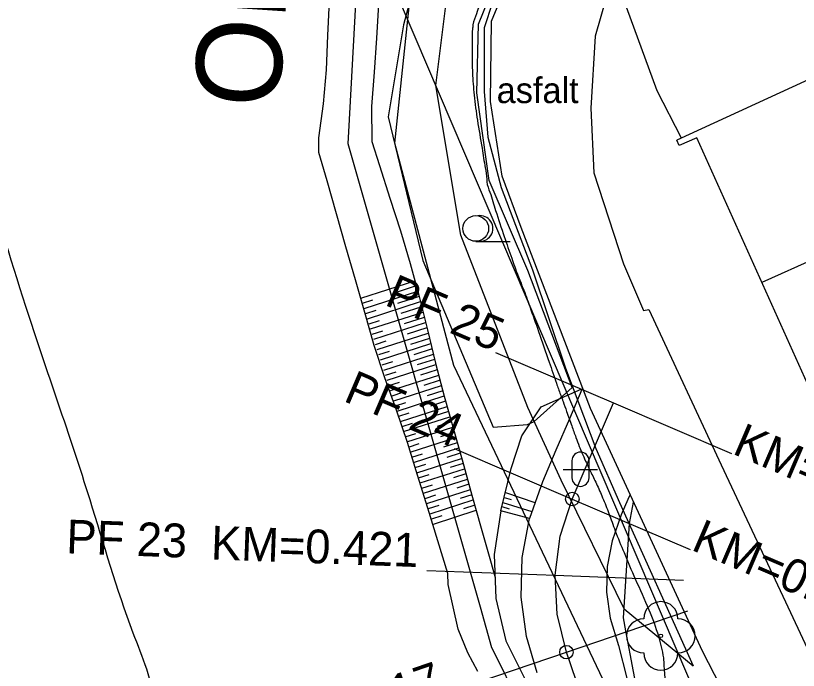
# Model space of a CAD drawing. Extents: x -478102 to -473059, y -1117705 to -1114104.
# Drawn here: x -476531.57 to -476485.84, y -1116837.52 to -1116799.24 of the extents above; entities that cross this region are included whole.
import ezdxf

# ---------------------------------------------------------------- set-up
doc = ezdxf.new("R2010")
doc.units = 0
for name, color, linetype in [('Budovy', 7, 'Continuous'), ('cestn___p____kop', 7, 'Continuous'), ('cesty', 7, 'Continuous'), ('hrana_L', 7, 'Continuous'), ('HraniceSouvislehoPorostu', 7, 'Continuous'), ('ObPÚ', 7, 'Continuous'), ('Ploty', 7, 'Continuous'), ('POLYGONY_SITUACE_PF', 7, 'Continuous'), ('POLYGONY_SITUACE_PF_POPISY', 7, 'Continuous'), ('POLYGONY_SITUACE_PO', 7, 'Continuous'), ('PopisneZnackyKultura', 7, 'Continuous'), ('PopisPovrchu', 7, 'Continuous'), ('RozhraniKultur', 7, 'Continuous'), ('RozhraniVozovky', 7, 'Continuous'), ('Teren_HranaSvahu', 7, 'Continuous'), ('Teren_PataSvahu', 7, 'Continuous'), ('TP_HS', 7, 'Continuous'), ('Vrstevnice_hlavni', 7, 'Continuous'), ('Vrstevnice_vedlejsi', 7, 'Continuous'), ('ZnackyStromu', 7, 'Continuous')]:
    doc.layers.add(name, color=color, linetype=linetype)

msp = doc.modelspace()

# ---------------------------------------------------------------- linework, layer by layer
for p, q in [((-476513.342, -1116800.401), (-476513.245, -1116798.403)), ((-476510.367, -1116798.561), (-476510.489, -1116800.557)), ((-476513.414, -1116802.4), (-476513.342, -1116800.401)), ((-476510.489, -1116800.557), (-476510.631, -1116802.552)), ((-476513.593, -1116804.393), (-476513.414, -1116802.4)), ((-476510.631, -1116802.552), (-476510.773, -1116804.548)), ((-476513.863, -1116806.381), (-476513.593, -1116804.393)), ((-476510.773, -1116804.548), (-476510.764, -1116806.596)), ((-476513.851, -1116807.251), (-476513.863, -1116806.381)), ((-476510.764, -1116806.596), (-476510.312, -1116808.011)), ((-476513.377, -1116808.907), (-476513.851, -1116807.251)), ((-476510.312, -1116808.011), (-476509.703, -1116809.917)), ((-476512.827, -1116810.83), (-476513.377, -1116808.907)), ((-476509.703, -1116809.917), (-476509.094, -1116811.822)), ((-476512.277, -1116812.753), (-476512.827, -1116810.83)), ((-476509.094, -1116811.822), (-476508.515, -1116813.737)), ((-476511.727, -1116814.676), (-476512.277, -1116812.753)), ((-476508.515, -1116813.737), (-476507.995, -1116815.669)), ((-476511.176, -1116816.599), (-476511.727, -1116814.676)), ((-476507.995, -1116815.669), (-476507.517, -1116817.612)), ((-476510.626, -1116818.521), (-476511.176, -1116816.599)), ((-476507.517, -1116817.612), (-476507.038, -1116819.556)), ((-476510, -1116820.422), (-476510.626, -1116818.521)), ((-476507.038, -1116819.556), (-476506.536, -1116821.493)), ((-476509.328, -1116822.309), (-476510, -1116820.422)), ((-476506.536, -1116821.493), (-476505.995, -1116823.419)), ((-476508.674, -1116824.202), (-476509.328, -1116822.309)), ((-476505.995, -1116823.419), (-476505.454, -1116825.344)), ((-476508.087, -1116826.114), (-476508.674, -1116824.202)), ((-476505.454, -1116825.344), (-476504.913, -1116827.27)), ((-476507.5, -1116828.026), (-476508.087, -1116826.114)), ((-476504.913, -1116827.27), (-476504.372, -1116829.196)), ((-476506.913, -1116829.938), (-476507.5, -1116828.026)), ((-476504.372, -1116829.196), (-476503.832, -1116831.121)), ((-476506.326, -1116831.85), (-476506.913, -1116829.938)), ((-476503.832, -1116831.121), (-476503.562, -1116832.084)), ((-476506.297, -1116832.488), (-476506.326, -1116831.85)), ((-476504.565, -1116837.587), (-476505.152, -1116836.498))]:
    msp.add_line(p, q)
for points in [[(-476511.41, -1116815.758), (-476508.245, -1116814.74)], [(-476508.163, -1116815.045), (-476509.461, -1116815.462)], [(-476511.217, -1116816.358), (-476508.081, -1116815.35)], [(-476511.314, -1116816.058), (-476510.696, -1116815.859)], [(-476511.025, -1116816.958), (-476507.923, -1116815.961)], [(-476507.999, -1116815.654), (-476509.268, -1116816.062)], [(-476511.121, -1116816.658), (-476510.503, -1116816.459)], [(-476507.848, -1116816.268), (-476509.075, -1116816.662)], [(-476510.832, -1116817.558), (-476507.772, -1116816.575)], [(-476507.697, -1116816.882), (-476508.882, -1116817.263)], [(-476510.928, -1116817.258), (-476510.31, -1116817.06)], [(-476510.639, -1116818.158), (-476507.621, -1116817.188)], [(-476510.735, -1116817.858), (-476510.117, -1116817.66)], [(-476510.446, -1116818.759), (-476507.47, -1116817.802)], [(-476507.546, -1116817.495), (-476508.689, -1116817.863)], [(-476510.542, -1116818.458), (-476509.924, -1116818.26)], [(-476507.395, -1116818.109), (-476508.496, -1116818.463)], [(-476510.253, -1116819.359), (-476507.319, -1116818.416)], [(-476507.243, -1116818.723), (-476508.303, -1116819.063)], [(-476510.349, -1116819.059), (-476509.732, -1116818.86)], [(-476510.06, -1116819.959), (-476507.168, -1116819.029)], [(-476510.156, -1116819.659), (-476509.539, -1116819.46)], [(-476509.867, -1116820.559), (-476507.016, -1116819.643)], [(-476507.092, -1116819.336), (-476508.11, -1116819.663)], [(-476509.964, -1116820.259), (-476509.346, -1116820.06)], [(-476506.936, -1116819.948), (-476507.917, -1116820.263)], [(-476509.674, -1116821.159), (-476506.857, -1116820.254)], [(-476506.778, -1116820.559), (-476507.724, -1116820.864)], [(-476509.771, -1116820.859), (-476509.153, -1116820.661)], [(-476509.481, -1116821.759), (-476506.699, -1116820.865)], [(-476509.578, -1116821.459), (-476508.96, -1116821.261)], [(-476509.288, -1116822.36), (-476506.54, -1116821.476)], [(-476506.62, -1116821.171), (-476507.531, -1116821.464)], [(-476509.385, -1116822.06), (-476508.767, -1116821.861)], [(-476506.455, -1116821.78), (-476507.338, -1116822.064)], [(-476509.192, -1116822.66), (-476508.574, -1116822.461)], [(-476509.095, -1116822.96), (-476506.37, -1116822.084)], [(-476506.285, -1116822.388), (-476507.146, -1116822.664)], [(-476508.903, -1116823.56), (-476506.199, -1116822.691)], [(-476508.999, -1116823.26), (-476508.381, -1116823.061)], [(-476508.71, -1116824.16), (-476506.029, -1116823.299)], [(-476506.114, -1116822.995), (-476506.953, -1116823.264)], [(-476508.806, -1116823.86), (-476508.188, -1116823.662)], [(-476505.944, -1116823.602), (-476506.76, -1116823.865)], [(-476508.613, -1116824.46), (-476507.995, -1116824.262)], [(-476508.517, -1116824.76), (-476505.858, -1116823.906)], [(-476505.773, -1116824.21), (-476506.567, -1116824.465)], [(-476508.324, -1116825.361), (-476505.687, -1116824.513)], [(-476508.42, -1116825.06), (-476507.802, -1116824.862)], [(-476508.131, -1116825.961), (-476505.517, -1116825.121)], [(-476505.602, -1116824.817), (-476506.374, -1116825.065)], [(-476508.227, -1116825.661), (-476507.61, -1116825.462)], [(-476505.431, -1116825.424), (-476506.181, -1116825.665)], [(-476508.034, -1116826.261), (-476507.417, -1116826.062)], [(-476507.938, -1116826.561), (-476505.346, -1116825.728)], [(-476505.261, -1116826.032), (-476505.988, -1116826.265)], [(-476507.745, -1116827.161), (-476505.176, -1116826.335)], [(-476507.842, -1116826.861), (-476507.224, -1116826.662)], [(-476507.552, -1116827.761), (-476505.005, -1116826.943)], [(-476505.09, -1116826.639), (-476505.795, -1116826.865)], [(-476507.649, -1116827.461), (-476507.031, -1116827.263)], [(-476504.92, -1116827.246), (-476505.602, -1116827.466)], [(-476507.456, -1116828.061), (-476506.838, -1116827.863)], [(-476507.359, -1116828.361), (-476504.834, -1116827.55)], [(-476504.749, -1116827.854), (-476505.409, -1116828.066)], [(-476493.611, -1116845.046), (-476495.024, -1116839.954), (-476495.915, -1116835.202), (-476496.059, -1116834.438), (-476495.701, -1116828.922), (-476495.475, -1116827.69)], [(-476507.166, -1116828.962), (-476504.664, -1116828.157)], [(-476507.263, -1116828.662), (-476506.645, -1116828.463)], [(-476505.152, -1116836.498), (-476505.719, -1116835.11), (-476506.297, -1116832.488)]]:
    msp.add_lwpolyline(points)
at = {"layer": 'Budovy'}
for p, q in [((-476480.507, -1116800.783), (-476492.94, -1116806.52)), ((-476491.78, -1116806.38), (-476492.81, -1116806.83)), ((-476478.1, -1116836.8), (-476491.78, -1116806.38)), ((-476492.81, -1116806.83), (-476492.94, -1116806.52)), ((-476483.847, -1116812.976), (-476487.978, -1116814.834))]:
    msp.add_line(p, q, dxfattribs=at)
at = {"layer": 'cestn___p____kop'}
for p, q in [((-476503.037, -1116827.414), (-476502.619, -1116827.536)), ((-476502.958, -1116827.111), (-476501.236, -1116827.702)), ((-476503.162, -1116827.938), (-476502.73, -1116828.066)), ((-476503.109, -1116827.712), (-476501.413, -1116828.222))]:
    msp.add_line(p, q, dxfattribs=at)
at = {"layer": 'cesty'}
for p, q in [((-476495.672, -1116827.229), (-476495.799, -1116827.525)), ((-476495.799, -1116827.525), (-476496.187, -1116828.43)), ((-476501.559, -1116828.638), (-476503.234, -1116828.185)), ((-476496.187, -1116828.43), (-476496.729, -1116829.943)), ((-476496.729, -1116829.943), (-476497.006, -1116831.435)), ((-476497.006, -1116831.435), (-476497.042, -1116832.952)), ((-476497.042, -1116832.952), (-476496.836, -1116834.458)), ((-476496.836, -1116834.458), (-476496.354, -1116836.065)), ((-476502.931, -1116835.794), (-476502.931, -1116835.794)), ((-476502.931, -1116835.794), (-476499.157, -1116843.34)), ((-476496.354, -1116836.065), (-476495.859, -1116837.974)), ((-476501.482, -1116840.818), (-476503.246, -1116837.201))]:
    msp.add_line(p, q, dxfattribs=at)
for points in [[(-476500.872, -1116822.107), (-476498.541, -1116821.07)], [(-476501.995, -1116823.801), (-476500.872, -1116822.107)], [(-476502.628, -1116825.706), (-476501.995, -1116823.801)], [(-476503.234, -1116828.185), (-476502.628, -1116825.706)], [(-476503.234, -1116828.185), (-476503.614, -1116830.746)], [(-476501.983, -1116830.916), (-476501.559, -1116828.638)], [(-476503.614, -1116830.746), (-476503.515, -1116833.316)], [(-476502.038, -1116833.233), (-476501.983, -1116830.916)], [(-476503.515, -1116833.316), (-476502.931, -1116835.794)], [(-476501.723, -1116835.529), (-476502.038, -1116833.233)], [(-476501.093, -1116837.661), (-476501.723, -1116835.529)], [(-476502.931, -1116835.794), (-476502.931, -1116835.794)]]:
    msp.add_lwpolyline(points, dxfattribs=at)
at = {"layer": 'hrana_L'}
for points in [[(-476498.486, -1116821.093), (-476499.222, -1116822.813)], [(-476499.222, -1116822.813), (-476500.009, -1116824.652)], [(-476500.009, -1116824.652), (-476500.796, -1116826.49)], [(-476500.796, -1116826.49), (-476501.559, -1116828.638)]]:
    msp.add_lwpolyline(points, dxfattribs=at)
at = {"layer": 'HraniceSouvislehoPorostu'}
msp.add_lwpolyline([(-476503.667, -1116823.297), (-476501.663, -1116823.142), (-476501.269, -1116822.977), (-476499.06, -1116820.987), (-476501.643, -1116814.144), (-476503.911, -1116808.879), (-476504.635, -1116803.762), (-476504.524, -1116799.738), (-476502.429, -1116794.533), (-476499.158, -1116791.112), (-476500.941, -1116790.007), (-476502.678, -1116789.287), (-476504.94, -1116790.065), (-476506.236, -1116792.421), (-476507.371, -1116793.97), (-476508.92, -1116799.781), (-476509.8, -1116805.165), (-476507.792, -1116813.551)], close=True, dxfattribs=at)
at = {"layer": 'ObPÚ'}
msp.add_lwpolyline([(-476357.4, -1116837.74), (-476422.93, -1116845.91), (-476427.37, -1116819.37), (-476430.29, -1116820.37), (-476436.91, -1116823.52), (-476455.71, -1116831.67), (-476450.1, -1116844.01), (-476476.04, -1116849.41), (-476482.1, -1116843.09), (-476483.67, -1116843.77), (-476488.84, -1116845.93), (-476490.13, -1116842.91), (-476508.98, -1116798.77)], dxfattribs=at)
at = {"layer": 'Ploty'}
msp.add_lwpolyline([(-476492.676, -1116806.398), (-476494.1, -1116803.644), (-476496.089, -1116798.145), (-476495.288, -1116796.97), (-476493.089, -1116793.815), (-476489.802, -1116790.11), (-476487.243, -1116787.893)], dxfattribs=at)
at = {"layer": 'POLYGONY_SITUACE_PF'}
for points in [[(-476503.542, -1116818.929), (-476496.647, -1116821.88), (-476489.752, -1116824.832)], [(-476505.947, -1116824.548), (-476499.052, -1116827.5), (-476492.157, -1116830.451)], [(-476507.547, -1116831.679), (-476500.052, -1116831.956), (-476492.557, -1116832.234)], [(-476506.491, -1116838.872), (-476499.392, -1116836.452), (-476492.293, -1116834.032)]]:
    msp.add_lwpolyline(points, dxfattribs=at)
at = {"layer": 'POLYGONY_SITUACE_PO'}
for points in [[(-476503.246, -1116837.201), (-476503.754, -1116836.198), (-476504.411, -1116833.82), (-476512.149, -1116806.742), (-476511.387, -1116792.829)], [(-476301.427, -1117045.065), (-476372.905, -1117052.019), (-476378.974, -1117051.908), (-476382.069, -1117051.436), (-476384.865, -1117050.444), (-476390.281, -1117047.7), (-476394.946, -1117043.817), (-476398.626, -1117038.989), (-476458.957, -1116938.029), (-476465.394, -1116926.586), (-476471.221, -1116914.82), (-476476.422, -1116902.765), (-476480.983, -1116890.454), (-476499.392, -1116836.452), (-476499.929, -1116834.228), (-476500.052, -1116831.944), (-476499.756, -1116829.676), (-476499.052, -1116827.5), (-476496.647, -1116821.88)]]:
    msp.add_lwpolyline(points, dxfattribs=at)
for centre in [(-476499.052, -1116827.5), (-476499.392, -1116836.452)]:
    msp.add_circle(centre, 0.395, dxfattribs=at)
at = {"layer": 'PopisneZnackyKultura'}
for p, q in [((-476504.689, -1116812.435), (-476502.689, -1116812.435)), ((-476499.077, -1116825.265), (-476499.077, -1116826.265)), ((-476498.077, -1116825.265), (-476498.077, -1116826.265)), ((-476499.577, -1116825.765), (-476497.577, -1116825.765))]:
    msp.add_line(p, q, dxfattribs=at)
msp.add_circle((-476504.689, -1116811.684), 0.75, dxfattribs=at)
for centre, radius, start, end in [((-476504.439, -1116811.684), 0.75, 260.4059, 99.5941), ((-476498.568, -1116825.258), 0.5, 0, 180), ((-476498.568, -1116826.258), 0.5, 180, 0)]:
    msp.add_arc(centre, radius, start, end, dxfattribs=at)
at = {"layer": 'RozhraniKultur'}
msp.add_lwpolyline([(-476490.21, -1116852.89), (-476505.97, -1116819.69), (-476509.41, -1116806.69), (-476507.1, -1116784.61)], dxfattribs=at)
at = {"layer": 'RozhraniVozovky'}
for points in [[(-476490.349, -1116825.506), (-476486.291, -1116834.14), (-476483.076, -1116841.048), (-476483.085, -1116841.925), (-476483.97, -1116842.691), (-476486.077, -1116843.648), (-476487.217, -1116843.934), (-476487.93, -1116843.214), (-476491.436, -1116836.397), (-476497.994, -1116822.204), (-476502.044, -1116811.617), (-476503.151, -1116808.629), (-476503.828, -1116804.26), (-476503.771, -1116799.56), (-476501.723, -1116794.622), (-476498.437, -1116790.602), (-476493.387, -1116786.282), (-476488.978, -1116781.97)], [(-476486.198, -1116785.025), (-476491.618, -1116789.798), (-476494.363, -1116792.808), (-476496.677, -1116796.826), (-476497.718, -1116800.431), (-476497.972, -1116804.656), (-476497.798, -1116808.431), (-476496.057, -1116813.746), (-476494.884, -1116816.479), (-476494.577, -1116816.424), (-476490.349, -1116825.506)]]:
    msp.add_lwpolyline(points, dxfattribs=at)
at = {"layer": 'Teren_HranaSvahu'}
msp.add_line((-476496.01, -1116833.929), (-476491.983, -1116837.253), dxfattribs=at)
msp.add_lwpolyline([(-476496.01, -1116833.929), (-476499.708, -1116826.401), (-476501.648, -1116822.147), (-476505.565, -1116812.08), (-476507.025, -1116803.334), (-476506.405, -1116798.313), (-476503.711, -1116792.546), (-476501.404, -1116790.625), (-476499.158, -1116791.112)], dxfattribs=at)
at = {"layer": 'Teren_PataSvahu'}
msp.add_lwpolyline([(-476499.158, -1116791.112), (-476502.208, -1116794.823), (-476503.708, -1116798.478), (-476504.196, -1116799.961), (-476504.191, -1116803.667), (-476503.982, -1116806.345), (-476503.215, -1116809.287), (-476501.38, -1116814.102), (-476499.454, -1116819.846), (-476497.667, -1116824.545), (-476496.291, -1116827.707), (-476491.983, -1116837.253)], dxfattribs=at)
at = {"layer": 'Vrstevnice_hlavni'}
for points in [[(-476516.851, -1116745.154), (-476516.407, -1116746.483), (-476514.652, -1116752.01), (-476513.242, -1116756.272), (-476512.175, -1116759.27), (-476511.452, -1116761.003), (-476510.834, -1116762.401), (-476510.32, -1116763.464), (-476509.911, -1116764.191), (-476509.686, -1116764.969), (-476509.645, -1116765.797), (-476509.788, -1116766.676), (-476509.864, -1116767.316), (-476509.873, -1116767.717), (-476509.813, -1116767.879), (-476509.447, -1116768.672), (-476508.772, -1116770.097), (-476507.79, -1116772.153), (-476506.994, -1116773.702), (-476506.384, -1116774.742), (-476505.959, -1116775.275), (-476505.223, -1116776.514), (-476504.175, -1116778.459), (-476502.816, -1116781.111), (-476501.986, -1116783.05), (-476501.687, -1116784.275), (-476501.716, -1116784.404), (-476501.794, -1116784.529), (-476501.876, -1116784.655), (-476501.918, -1116784.786), (-476501.862, -1116785.683), (-476501.521, -1116786.966), (-476500.892, -1116788.635), (-476500.503, -1116789.743), (-476500.375, -1116790.019), (-476500.334, -1116790.157), (-476500.351, -1116790.291), (-476500.437, -1116790.278), (-476500.545, -1116790.32), (-476500.674, -1116790.416), (-476500.825, -1116790.567), (-476500.993, -1116790.734), (-476501.178, -1116790.917), (-476501.381, -1116791.115), (-476501.65, -1116791.544), (-476501.983, -1116792.205), (-476502.382, -1116793.096), (-476502.697, -1116793.835), (-476502.928, -1116794.421), (-476503.075, -1116794.854), (-476503.351, -1116795.612), (-476503.755, -1116796.696), (-476504.288, -1116798.104), (-476504.653, -1116799.131), (-476504.852, -1116799.775), (-476504.883, -1116800.036), (-476504.898, -1116800.591), (-476504.898, -1116801.439), (-476504.883, -1116802.579), (-476504.782, -1116803.886), (-476504.595, -1116805.358), (-476504.322, -1116806.996), (-476504.138, -1116808.141), (-476504.043, -1116808.793), (-476504.038, -1116808.953), (-476503.866, -1116809.567), (-476503.528, -1116810.636), (-476503.024, -1116812.159), (-476502.59, -1116813.421), (-476502.228, -1116814.421), (-476501.936, -1116815.159), (-476501.534, -1116816.252), (-476501.021, -1116817.7), (-476500.398, -1116819.504), (-476499.972, -1116820.733), (-476499.743, -1116821.386), (-476499.711, -1116821.465), (-476499.591, -1116821.797), (-476499.382, -1116822.382), (-476499.086, -1116823.219), (-476498.839, -1116823.9), (-476498.641, -1116824.424), (-476498.491, -1116824.791), (-476498.274, -1116825.277), (-476497.99, -1116825.882), (-476497.637, -1116826.604), (-476497.279, -1116827.424), (-476496.914, -1116828.341), (-476496.542, -1116829.355), (-476496.028, -1116830.632), (-476495.371, -1116832.172), (-476494.572, -1116833.974), (-476494.02, -1116835.509), (-476493.715, -1116836.779)], [(-476493.715, -1116836.779), (-476493.657, -1116837.782), (-476493.454, -1116838.814), (-476493.106, -1116839.874), (-476492.613, -1116840.964), (-476491.914, -1116842.563), (-476491.008, -1116844.672), (-476489.895, -1116847.291), (-476489.121, -1116849.068), (-476488.687, -1116850.006), (-476488.591, -1116850.102), (-476488.194, -1116850.666), (-476487.494, -1116851.699), (-476486.491, -1116853.199), (-476485.812, -1116854.196), (-476485.456, -1116854.691), (-476485.422, -1116854.683), (-476485.307, -1116854.78), (-476485.109, -1116854.984), (-476484.829, -1116855.293), (-476484.118, -1116857.163), (-476482.975, -1116860.594), (-476481.402, -1116865.585), (-476480.12, -1116869.665), (-476479.13, -1116872.833), (-476478.431, -1116875.088), (-476477.86, -1116876.887), (-476477.416, -1116878.229), (-476477.099, -1116879.115), (-476476.855, -1116880.078), (-476476.685, -1116881.12), (-476476.587, -1116882.239), (-476476.21, -1116884.112), (-476475.555, -1116886.737), (-476474.62, -1116890.115), (-476473.657, -1116893.01), (-476472.666, -1116895.422), (-476471.647, -1116897.352), (-476470.243, -1116900.412), (-476468.455, -1116904.603), (-476466.283, -1116909.925), (-476464.77, -1116913.634), (-476463.916, -1116915.731), (-476463.721, -1116916.214), (-476463.617, -1116916.722), (-476463.603, -1116917.256), (-476463.679, -1116917.815), (-476463.509, -1116918.911), (-476463.093, -1116920.547), (-476462.43, -1116922.72), (-476462.028, -1116926.548), (-476461.886, -1116932.03), (-476462.123, -1116946.304)]]:
    msp.add_spline(points, degree=3, dxfattribs=at)
at = {"layer": 'Vrstevnice_vedlejsi'}
msp.add_spline([(-476571.958, -1116704.162), (-476571.904, -1116704.215), (-476571.688, -1116704.429), (-476571.311, -1116704.803), (-476570.773, -1116705.338), (-476569.946, -1116706.363), (-476568.83, -1116707.879), (-476567.427, -1116709.886), (-476566.203, -1116711.628), (-476565.16, -1116713.105), (-476564.298, -1116714.317), (-476563.772, -1116715.225), (-476563.581, -1116715.829), (-476563.726, -1116716.129), (-476564.073, -1116716.669), (-476564.621, -1116717.45), (-476565.371, -1116718.471), (-476565.697, -1116719.715), (-476565.599, -1116721.18), (-476565.077, -1116722.867), (-476563.322, -1116725.926), (-476560.334, -1116730.356), (-476556.114, -1116736.158), (-476552.562, -1116741.631), (-476549.677, -1116746.776), (-476547.46, -1116751.593), (-476545.693, -1116756.042), (-476544.374, -1116760.122), (-476543.504, -1116763.833), (-476542.206, -1116769.314), (-476540.482, -1116776.566), (-476538.329, -1116785.587), (-476536.736, -1116792.746), (-476535.702, -1116798.044), (-476535.228, -1116801.481), (-476533.66, -1116807.541), (-476530.999, -1116816.224), (-476527.246, -1116827.53), (-476524.726, -1116835.32), (-476523.44, -1116839.595), (-476523.389, -1116840.354), (-476523.331, -1116841.083), (-476523.266, -1116841.783), (-476523.195, -1116842.453), (-476522.8, -1116844.094), (-476522.082, -1116846.705), (-476521.041, -1116850.288), (-476519.77, -1116855.097), (-476518.27, -1116861.134), (-476516.539, -1116868.399), (-476515.387, -1116873.283), (-476514.813, -1116875.785), (-476514.818, -1116875.907), (-476514.695, -1116876.43), (-476514.444, -1116877.353), (-476514.064, -1116878.676), (-476513.598, -1116880.016), (-476513.045, -1116881.373), (-476512.404, -1116882.746), (-476510.965, -1116886.684), (-476508.726, -1116893.188), (-476505.69, -1116902.257), (-476503.32, -1116909.062), (-476501.617, -1116913.604), (-476500.581, -1116915.881), (-476499.982, -1116918.695), (-476499.82, -1116922.044), (-476500.095, -1116925.93), (-476500.622, -1116930.955), (-476501.399, -1116937.119), (-476502.428, -1116944.424), (-476503.284, -1116951.043), (-476503.968, -1116956.977), (-476504.479, -1116962.226), (-476505.481, -1116968.833), (-476506.974, -1116976.798), (-476508.959, -1116986.121), (-476510.49, -1116993.241), (-476511.568, -1116998.159), (-476512.192, -1117000.873), (-476513.406, -1117005.693), (-476515.21, -1117012.619), (-476517.605, -1117021.651), (-476519.543, -1117028.708), (-476521.025, -1117033.789), (-476522.05, -1117036.895), (-476522.813, -1117039.387), (-476523.316, -1117041.266), (-476523.557, -1117042.532), (-476525.061, -1117047.398), (-476527.83, -1117055.865), (-476531.861, -1117067.933), (-476534.429, -1117077.623), (-476535.532, -1117084.937), (-476535.172, -1117089.874), (-476535.368, -1117095.964), (-476536.121, -1117103.207)], degree=3, dxfattribs=at)
at = {"layer": 'ZnackyStromu'}
msp.add_circle((-476493.876, -1116835.5), 0.1, dxfattribs=at)
for centre, start, end in [((-476493.876, -1116834.5), 0, 180), ((-476494.876, -1116835.5), 90, 270), ((-476492.876, -1116835.5), 270, 90), ((-476493.876, -1116836.5), 180, 0)]:
    msp.add_arc(centre, 1, start, end, dxfattribs=at)

# ---------------------------------------------------------------- texts
at = {"layer": 'POLYGONY_SITUACE_PF_POPISY'}
for s, rotation, p in [('PF 25', 336.8263, (-476510.083, -1116816.129)), ('PF 24', 336.8263, (-476512.488, -1116821.748)), ('KM=0.432', 336.8263, (-476489.763, -1116824.827)), ('PF 23', 357.8817, (-476528.64, -1116830.673)), ('KM=0.426', 336.8263, (-476492.169, -1116830.446)), ('KM=0.421', 357.8817, (-476520.187, -1116831.03)), ('KM=0.417', 18.8241, (-476517.972, -1116842.754))]:
    msp.add_text(s, height=1.9765, rotation=rotation, dxfattribs=at).set_placement(p)
at = {"layer": 'PopisPovrchu'}
msp.add_text('asfalt', height=1.5, dxfattribs=at).set_placement((-476503.469, -1116804.354))
at = {"layer": 'TP_HS'}
msp.add_text('OP1', height=5, rotation=86.1911, dxfattribs=at).set_placement((-476516.19, -1116804.728))

doc.saveas('drawing.dxf')
